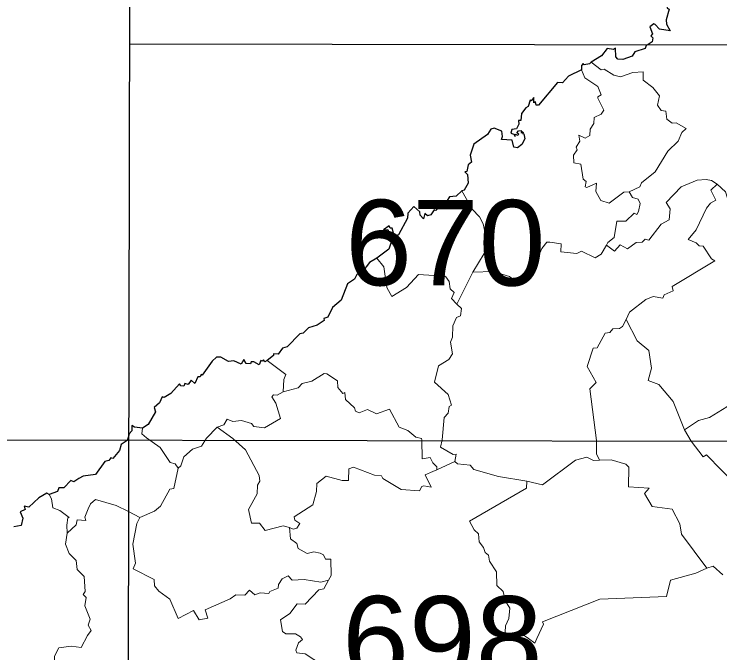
# Model space of a CAD drawing. Extents: x 483840 to 488445, y 4386047 to 4389027.
# Drawn here: x 487952.7 to 488113.7, y 4388006.1 to 4388151.7 of the extents above; entities that cross this region are included whole.
import ezdxf
from ezdxf.enums import TextEntityAlignment as Align

# ---------------------------------------------------------------- set-up
doc = ezdxf.new("R2010")
doc.units = 0
doc.header["$LTSCALE"] = 4
doc.linetypes.add('DOTTED', pattern=[1.5, 0.3, -1.2])
for name, color, linetype, lineweight in [('1', 7, 'Continuous', 13), ('2', 7, 'DOTTED', 13), ('3', 7, 'Continuous', 25)]:
    doc.layers.add(name, color=color, linetype=linetype, lineweight=lineweight)

msp = doc.modelspace()

# ---------------------------------------------------------------- linework, layer by layer
at = {"layer": '1', "lineweight": 25}
for p, q in [((487978.6, 4387873.99), (487979.3, 4388235.3)), ((487979.13, 4388144.96), (488394.81, 4388144.16)), ((487840.39, 4388054.9), (488394.63, 4388053.84))]:
    msp.add_line(p, q, dxfattribs=at)
at = {"layer": '3', "lineweight": 13}
for p, q in [((488074.25, 4388099.74), (488074.92, 4388099.74)), ((488087.85, 4388099.09), (488088.13, 4388099.68)), ((488057.38, 4388092.94), (488053.69, 4388085.65)), ((487999.04, 4388057.56), (488002.62, 4388055.03)), ((488053.23, 4388049.76), (488049.16, 4388047.86)), ((488049.16, 4388047.86), (488048.19, 4388047.51)), ((487978.82, 4388038.34), (487981.44, 4388036.98))]:
    msp.add_line(p, q, dxfattribs=at)
at = {"layer": '3'}
msp.add_line((487978.96, 4388056.07), (487978.76, 4388055.2), dxfattribs=at)
for points in [[(488109.21, 4388156.83), (488108.27, 4388156.85), (488107.5, 4388155.16), (488106.74, 4388154.73), (488106.29, 4388155.64), (488104.82, 4388156.58), (488103.69, 4388156.53), (488102.64, 4388155.81), (488101.54, 4388154), (488101.66, 4388153.1), (488102.11, 4388152.87), (488101.42, 4388150.45), (488101.52, 4388149.41), (488102.36, 4388147.91), (488099.88, 4388148.26), (488098.92, 4388149.35)], [(488098.92, 4388149.35), (488098.59, 4388149.53), (488097.72, 4388148.84), (488098.34, 4388147.23), (488097.91, 4388146.79), (488098.39, 4388146.28), (488098.22, 4388145.4), (488097.33, 4388144.8)], [(488097.33, 4388144.8), (488096.86, 4388144.6), (488096.63, 4388143.9), (488094.29, 4388143.12), (488093.69, 4388142.17), (488091.56, 4388141.39), (488090.4, 4388141.42), (488089.98, 4388142), (488089.87, 4388143.99), (488089.44, 4388143.67), (488087.97, 4388143.91), (488086.68, 4388142.25), (488084.32, 4388140.8)], [(488084.32, 4388140.8), (488083.98, 4388140.38), (488082.74, 4388140.17), (488082.53, 4388140.45), (488082.13, 4388139.98), (488082.15, 4388139.06)], [(488082.15, 4388139.06), (488079.19, 4388137.55), (488077.8, 4388136.08), (488076.65, 4388136.13), (488072.28, 4388131), (488071.76, 4388130.98), (488071.61, 4388131.71), (488071.26, 4388131.51), (488071.23, 4388132.73), (488070.66, 4388131.92), (488070.44, 4388132.13), (488069.93, 4388130.63), (488069.43, 4388130.33)], [(488069.43, 4388130.33), (488068.41, 4388129.09), (488068.26, 4388127.51), (488067.78, 4388127.46), (488067.86, 4388126.66), (488067.28, 4388125.58), (488066.27, 4388125.44), (488066, 4388124.61), (488066.72, 4388124.38), (488067.03, 4388123.82), (488066.98, 4388124.39), (488067.63, 4388124.14), (488067.8, 4388124.39), (488067.39, 4388124.66), (488067.79, 4388125.15), (488068.36, 4388125.16), (488068.46, 4388124.62), (488068.53, 4388125), (488068.87, 4388124.74), (488068.67, 4388124.55), (488069, 4388124.47), (488069.18, 4388123.32), (488068.53, 4388121.97), (488067.54, 4388121.26), (488066.71, 4388121.37), (488066.3, 4388122.96), (488063.91, 4388123.18), (488064.08, 4388123.84)], [(488064.08, 4388123.84), (488063.94, 4388125.03), (488062.18, 4388125.76), (488061.45, 4388125.49), (488060.71, 4388124.3), (488057.57, 4388122.1), (488056.7, 4388119.54), (488057.05, 4388118), (488056.25, 4388117.35), (488055.98, 4388115.84), (488055.54, 4388115.8), (488056.13, 4388115.18), (488056.29, 4388113.16), (488055.33, 4388111.59), (488054.84, 4388111.45)], [(488054.84, 4388111.45), (488053.57, 4388110.21), (488052.01, 4388110.09), (488051.35, 4388108.99), (488050.87, 4388108.97), (488048.88, 4388106.95), (488048.54, 4388107.12)], [(488048.54, 4388107.12), (488047.74, 4388106), (488046.99, 4388105.77), (488046.36, 4388106.31), (488046.07, 4388105.03), (488045.34, 4388105.89), (488045.29, 4388106.69), (488043.92, 4388107.91), (488042.53, 4388106.35), (488042.46, 4388105.21), (488040.43, 4388101.38), (488039.51, 4388100.91), (488038.97, 4388102.9)], [(488038.97, 4388102.9), (488038.46, 4388102.92), (488038.28, 4388103.44), (488036.94, 4388102.53), (488037.97, 4388102.61), (488038.79, 4388099.94)], [(488038.79, 4388099.94), (488038.2, 4388098.17), (488035.44, 4388096.1)], [(488035.44, 4388096.1), (488033.8, 4388095.09), (488032.05, 4388092.86), (488030.91, 4388092.37), (488030.34, 4388091.3), (488028.73, 4388090.22), (488027.35, 4388086.56), (488025.33, 4388084.82), (488024.25, 4388082.65), (488023.38, 4388082.36), (488023.45, 4388081.86)], [(488023.45, 4388081.86), (488021.86, 4388080.83), (488019.89, 4388080.22), (488018.66, 4388079.03), (488017.9, 4388078.85), (488014.99, 4388075.87), (488013.91, 4388075.62), (488012.92, 4388074.23), (488011.92, 4388074.32), (488011.9, 4388073.93), (488010.42, 4388072.74)], [(488010.42, 4388072.74), (488009.92, 4388072.48), (488009.62, 4388072.95), (488009.33, 4388072.64), (488008.97, 4388072.81), (488008.64, 4388071.82), (488007.44, 4388072.49), (488006.77, 4388072.48), (488006.65, 4388071.98), (488005.66, 4388072.06), (488005.13, 4388072.97), (488004.55, 4388071.91), (488002.86, 4388072.68), (488001.66, 4388072.52), (487999.87, 4388073.55), (487998.92, 4388073.52), (487997.87, 4388072.65), (487995.59, 4388069.4)], [(487995.59, 4388069.4), (487995.36, 4388069.62), (487995.2, 4388069.09), (487994.6, 4388069.02), (487993.93, 4388067.55), (487993.11, 4388068.3), (487992.4, 4388067.31), (487991.64, 4388067.55), (487991.42, 4388066.9), (487990.73, 4388066.97), (487990.44, 4388067.49), (487988.47, 4388065.26), (487986.98, 4388064.34), (487986.49, 4388064.51), (487985.86, 4388063.11), (487984.67, 4388062.04), (487984.95, 4388061.05)], [(487984.95, 4388061.05), (487983.29, 4388058.17), (487981.99, 4388057.38)], [(487981.99, 4388057.38), (487980.16, 4388057.56), (487979.6, 4388057.95), (487979.57, 4388056.76), (487978.96, 4388056.07)], [(487978.76, 4388055.2), (487978.5, 4388054.54), (487977.15, 4388053.64), (487976.79, 4388052.26), (487975.28, 4388050.45), (487974.79, 4388050.57), (487974.33, 4388049.98), (487973.44, 4388049.76), (487971.29, 4388046.8), (487968.51, 4388046.4), (487967.47, 4388045.86)], [(487967.47, 4388045.86), (487966.35, 4388045.1), (487965.65, 4388045.41), (487964.11, 4388043.76), (487962.96, 4388043.73), (487962.67, 4388042.93), (487960.73, 4388042.23)], [(487960.73, 4388042.23), (487960.22, 4388042.52), (487958.39, 4388041.46), (487956.12, 4388039.38), (487955.03, 4388039.6), (487955.28, 4388038.81), (487954.1, 4388038.28), (487954.75, 4388036.84), (487954.39, 4388035.2), (487952.69, 4388034.85)]]:
    msp.add_lwpolyline(points, dxfattribs=at)
at = {"layer": '3', "lineweight": 13}
for points in [[(488084.32, 4388140.8), (488086.58, 4388139.06), (488087.31, 4388139.15), (488089.49, 4388137.83), (488090.99, 4388137.43), (488093.82, 4388138.39), (488096.18, 4388138.58), (488096.21, 4388136.7), (488098.37, 4388135.03), (488099.92, 4388133.07), (488099.43, 4388130.95), (488100.26, 4388129.76), (488101.33, 4388129.58), (488101.57, 4388127.76), (488102.78, 4388126.88), (488103.73, 4388126.95), (488105.95, 4388125.66), (488105.03, 4388124.74), (488104.13, 4388122.8), (488101.84, 4388120.52), (488098.88, 4388115.76), (488095.78, 4388113.28), (488095.45, 4388112.37), (488093, 4388111.23)], [(488085.86, 4388132.53), (488085.83, 4388132.87), (488086.59, 4388133.31), (488085.82, 4388135.21), (488082.9, 4388137.21), (488082.15, 4388139.06)], [(488093, 4388111.23), (488091.79, 4388111.16), (488088.43, 4388108.67), (488086.55, 4388109.27), (488085.36, 4388111.27), (488085.51, 4388113.17), (488083.34, 4388112.18), (488082.99, 4388112.36), (488083.21, 4388113.55), (488082.48, 4388114.11), (488081.95, 4388117.52), (488080.34, 4388117.81), (488080.32, 4388119.6), (488081.17, 4388120.82), (488080.94, 4388121.38), (488081.77, 4388122.74), (488081.53, 4388124.11), (488082.96, 4388123.48), (488084.02, 4388124.08), (488084.1, 4388125.47), (488084.92, 4388126.8), (488085.03, 4388128.14), (488086.63, 4388128.91), (488087.25, 4388129.8), (488085.86, 4388132.53)], [(488113.04, 4388112.95), (488111.76, 4388113.82), (488110.52, 4388114.02), (488108.46, 4388113.87), (488104.85, 4388112.36), (488101.39, 4388108.75), (488102.37, 4388107.31), (488102.13, 4388104.86), (488100.3, 4388103.82), (488097.45, 4388100.17), (488096.64, 4388100.4), (488095.92, 4388099.73), (488094.58, 4388099.64)], [(488113.04, 4388112.95), (488111.62, 4388111.6), (488112.77, 4388109.34), (488111.52, 4388108.64), (488110.59, 4388107.46), (488108.3, 4388102.57), (488106.44, 4388100.35), (488108.23, 4388099.58)], [(488113.04, 4388112.95), (488114.99, 4388111.18), (488115.38, 4388109.76), (488116.38, 4388109.5), (488117.02, 4388107.33), (488117.72, 4388106.93)], [(488054.84, 4388111.45), (488057.19, 4388107.29), (488058.9, 4388105.49), (488059.73, 4388103.9), (488060.36, 4388100.76), (488060.88, 4388099.81)], [(488093, 4388111.23), (488093.74, 4388109.94), (488095.05, 4388109.53), (488095.53, 4388108.56), (488095.13, 4388106.7), (488094.73, 4388106.05), (488094.14, 4388106.35), (488092.2, 4388104.52), (488090.2, 4388104.51), (488089.54, 4388100.84), (488088.13, 4388099.68)], [(488057.38, 4388092.94), (488061.21, 4388099.27), (488060.88, 4388099.81)], [(488057.38, 4388092.94), (488062.01, 4388093.08), (488065.73, 4388091.89), (488067.62, 4388090.43), (488069.89, 4388092.95), (488070.32, 4388094.19), (488072.32, 4388096.56), (488073.1, 4388098.33), (488074.25, 4388099.74)], [(488087.85, 4388099.09), (488086.57, 4388097), (488085.2, 4388096.19), (488082.12, 4388097.73), (488081.04, 4388097.19), (488077.39, 4388097.51), (488077.5, 4388099.33), (488074.92, 4388099.74)], [(488087.85, 4388099.09), (488089.65, 4388097.68), (488090.93, 4388099.11), (488092.6, 4388098.22), (488094.58, 4388099.64)], [(488108.23, 4388099.58), (488108.98, 4388098.94), (488109.84, 4388098.86), (488111.74, 4388095.93), (488112.51, 4388095.48), (488102.76, 4388089.62), (488103.02, 4388088.66), (488100.98, 4388087.74), (488100.67, 4388086.99), (488098.44, 4388087.33), (488096.82, 4388086.65), (488093.05, 4388083.81), (488092.27, 4388082.13)], [(488035.44, 4388096.1), (488037.03, 4388094.12), (488037.76, 4388089.45), (488038.89, 4388087.4), (488042.21, 4388089.42), (488044.96, 4388092.39), (488048.45, 4388092.14)], [(488053.69, 4388085.65), (488052.45, 4388086.89), (488053.1, 4388088.3), (488052.14, 4388089.1), (488051.93, 4388090.81), (488051.22, 4388091.83), (488050.38, 4388092.4), (488048.45, 4388092.14)], [(488053.69, 4388085.65), (488054.72, 4388084.65), (488054.51, 4388082.95), (488053.58, 4388082.54), (488052.78, 4388080.67), (488052.73, 4388078.13), (488052.27, 4388076.98), (488052.67, 4388074.29), (488051.85, 4388073), (488049.53, 4388071.55), (488048.6, 4388067.8), (488051.72, 4388065.04), (488052.51, 4388062.58), (488051.95, 4388062.29), (488051.73, 4388060.76), (488050.77, 4388059.76), (488050.33, 4388054.7)], [(488092.27, 4388082.13), (488091.44, 4388080.49), (488090.78, 4388080.04), (488089.27, 4388080.03), (488088.55, 4388079.15), (488087.5, 4388079), (488085.71, 4388075.64), (488084.8, 4388075.56), (488083.41, 4388071.4), (488085.45, 4388067.77), (488084.05, 4388066.35), (488085.55, 4388054.53)], [(488092.27, 4388082.13), (488094.78, 4388077.28), (488097.49, 4388075.03), (488098.07, 4388071.04), (488097.33, 4388068.23), (488099.78, 4388067.28), (488103.05, 4388063.45), (488105.62, 4388057.01), (488107.11, 4388054.42)], [(488010.42, 4388072.74), (488014.74, 4388069.56), (488014.24, 4388068.42), (488014.13, 4388065.6)], [(488014.13, 4388065.6), (488017.52, 4388066.58), (488018.39, 4388067.51), (488020.63, 4388068.05), (488023.46, 4388069.84), (488024.03, 4388069.73), (488026.52, 4388068.15), (488026.58, 4388066.61), (488027.71, 4388065.28), (488028.17, 4388065.46), (488028.32, 4388063.88), (488030.36, 4388062.02), (488030.6, 4388061.23), (488031.41, 4388060.84), (488033.3, 4388061.59), (488035.34, 4388060.63), (488038.32, 4388061.67), (488040.55, 4388057.55), (488042.55, 4388056.81), (488044.35, 4388055.3), (488045.65, 4388055.03), (488045.69, 4388054.73)], [(488014.13, 4388065.6), (488012.71, 4388064.84), (488011.9, 4388064.95), (488011.54, 4388064.5), (488012.43, 4388063.03), (488013.47, 4388059.54), (488009.82, 4388057.42), (488007.38, 4388057.7), (488006.88, 4388058.38), (488004.56, 4388059.09), (488002.6, 4388058.86), (488001.34, 4388059.37), (488000.57, 4388058.15), (487999.04, 4388057.56), (487996.64, 4388055.07)], [(488105.62, 4388057.01), (488108.78, 4388059.1), (488111.28, 4388059.81), (488115.25, 4388062.24), (488117.55, 4388064.55)], [(487981.99, 4388057.38), (487981.87, 4388056.08), (487982.9, 4388055.17)], [(487982.9, 4388055.17), (487986.01, 4388052.93), (487988.33, 4388049.52), (487989.44, 4388049.2), (487990.14, 4388048.25)], [(487996.64, 4388055.07), (487995.45, 4388053.26), (487993.43, 4388052.58), (487991.48, 4388050.8), (487990.74, 4388048.75), (487990.14, 4388048.25)], [(488002.62, 4388055.03), (488005.48, 4388052.42), (488008.63, 4388046.54), (488008.77, 4388045.31), (488008.24, 4388044.36), (488008.15, 4388042.4), (488006.22, 4388038.84), (488006.85, 4388035.68), (488008.69, 4388035.67), (488009.99, 4388034.01), (488014.07, 4388035.07), (488015.54, 4388034.7)], [(488045.69, 4388054.73), (488045.79, 4388050.37), (488047.59, 4388050.7), (488048.2, 4388049.43)], [(488050.33, 4388054.7), (488049.97, 4388053.02), (488052.82, 4388051.34), (488053.52, 4388051.39), (488053.23, 4388049.76)], [(488085.55, 4388054.53), (488085.53, 4388051.51), (488086.21, 4388050.03)], [(488107.11, 4388054.42), (488109.86, 4388050.8), (488110.66, 4388051.29), (488117.47, 4388044.28)], [(488048.2, 4388049.43), (488049.1, 4388048.57), (488049.16, 4388047.86)], [(488069.69, 4388045.26), (488063.2, 4388046.35), (488057.55, 4388047.97), (488056.77, 4388048.93), (488053.85, 4388049.2), (488053.23, 4388049.76)], [(488086.21, 4388050.03), (488084.85, 4388049.95), (488083.34, 4388050.77), (488080.77, 4388050.08), (488073.2, 4388044.45), (488069.69, 4388045.26)], [(488086.21, 4388050.03), (488088.86, 4388050.15), (488092.23, 4388049.18), (488092.91, 4388048.48), (488092.83, 4388044.02), (488097.54, 4388043.66), (488096.52, 4388042.48), (488098.24, 4388039.53), (488102.76, 4388038.89), (488104.53, 4388035.55), (488104.92, 4388033.21), (488110.71, 4388025.43)], [(487990.14, 4388048.25), (487989.19, 4388043.63), (487988.26, 4388043.42), (487986.14, 4388039.57), (487984.78, 4388038.45), (487981.44, 4388036.98)], [(488015.54, 4388034.7), (488016.39, 4388034.35), (488017.22, 4388034.57), (488017.86, 4388035.59), (488016.72, 4388036.35), (488016.63, 4388037.11), (488020.86, 4388039.85), (488021.71, 4388042.9), (488021.8, 4388044.71), (488023.87, 4388046.4), (488027.53, 4388045.4), (488028.99, 4388045.42), (488029.05, 4388048.12), (488030.1, 4388048.43), (488034.94, 4388046.63), (488036.52, 4388046.48), (488036.79, 4388045.87), (488041.01, 4388043.41), (488045.19, 4388043.07), (488045.71, 4388044.07), (488046.18, 4388044.24), (488047.81, 4388043.92), (488046.44, 4388046.72), (488048.19, 4388047.51)], [(488069.69, 4388045.26), (488069.58, 4388043.7), (488056.61, 4388036.17), (488057.68, 4388034.2), (488058.65, 4388033.28), (488058.8, 4388031.44), (488059.77, 4388030.19), (488060.15, 4388028.98), (488060.91, 4388028.38), (488061.14, 4388027.02), (488062.71, 4388024.62), (488062.84, 4388021.48), (488064.23, 4388020.1), (488064.81, 4388017.95), (488065.8, 4388016.3), (488065.52, 4388013.94), (488064.79, 4388012.33), (488064.64, 4388009.47)], [(487960.73, 4388042.23), (487961.29, 4388041.27), (487961.54, 4388039.22), (487963.2, 4388038.59), (487965.27, 4388037.01), (487964.99, 4388036.93), (487964.77, 4388035.25), (487964.84, 4388033.44)], [(487964.84, 4388033.44), (487966.92, 4388035.35), (487967.12, 4388036.44), (487969.07, 4388036.34), (487968.9, 4388037.06), (487969.62, 4388038.98), (487970.18, 4388040.11), (487971.33, 4388041.1), (487975.98, 4388039.73), (487978.82, 4388038.34)], [(487981.44, 4388036.98), (487980.76, 4388035.64), (487979.78, 4388030.91), (487980.39, 4388026.57), (487979.89, 4388025.27), (487984.66, 4388022.85), (487984.78, 4388021.4), (487985.75, 4388020.21), (487988.28, 4388018.37), (487990.18, 4388013.94), (487993.63, 4388015.76), (487994.93, 4388013.64), (487996.88, 4388014.07), (487996.29, 4388015.94), (488002.02, 4388018.45), (488003.31, 4388019.36), (488005.37, 4388019.31), (488006.43, 4388020.44), (488007.64, 4388019.4), (488008.82, 4388019.84), (488010.82, 4388019.69), (488011.07, 4388020.11), (488012.98, 4388020.89), (488013.03, 4388021.74), (488013.87, 4388023.01), (488015.24, 4388023.69), (488016.15, 4388022.7), (488018.85, 4388022.86), (488022.67, 4388022.25), (488024.41, 4388022.73)], [(487964.84, 4388033.44), (487964.46, 4388030.92), (487965.27, 4388028.79), (487966.9, 4388027.21), (487967.15, 4388025.12), (487968.75, 4388023.57), (487968.96, 4388020.09), (487968.46, 4388019.47), (487969.17, 4388018.77), (487968.87, 4388016.88), (487970.06, 4388013.86), (487969.63, 4388012.48), (487970.33, 4388011.23), (487969.45, 4388010.12)], [(488015.54, 4388034.7), (488015.79, 4388032.11), (488017.18, 4388031.06), (488017.55, 4388029.9), (488019.58, 4388028.77), (488021.08, 4388029.19), (488022.56, 4388028.87), (488023.28, 4388028.45), (488023.75, 4388027.51), (488024.98, 4388027.53), (488025.01, 4388023.81), (488024.41, 4388022.73)], [(488110.71, 4388025.43), (488108.22, 4388024.31), (488102.42, 4388022.68), (488101.47, 4388018.96), (488086.3, 4388018.38), (488073.26, 4388013.2), (488073.49, 4388012.71), (488071.96, 4388009.43)], [(488114.31, 4388023.95), (488112.13, 4388025.87), (488110.71, 4388025.43)], [(488024.41, 4388022.73), (488023.39, 4388020.74), (488022.21, 4388020.51), (488019.11, 4388017.23), (488017.28, 4388017.32), (488015.59, 4388015.12), (488013.49, 4388013.7), (488013.97, 4388010.98), (488014.71, 4388010.49), (488016.93, 4388010.48), (488018.07, 4388009.76)], [(487969.45, 4388010.12), (487968.06, 4388007.38), (487965.76, 4388007.7), (487962.94, 4388007.28), (487961.95, 4388005.42), (487961.92, 4388002.51), (487961.13, 4388000.06), (487963.22, 4387998.37), (487964.92, 4387997.77), (487965.37, 4387995.93), (487966.74, 4387996.15), (487965.14, 4387993.92), (487963.19, 4387992.85), (487962.45, 4387990.37), (487958.7, 4387987.57), (487958.35, 4387985.3), (487956.45, 4387983.55), (487955.58, 4387980.55), (487954.04, 4387977.56)], [(488018.07, 4388009.76), (488018.47, 4388009.15), (488017.59, 4388008.42), (488016.99, 4388006.79), (488017.24, 4388006.18), (488019.09, 4388005.91), (488023.1, 4388003.37), (488025.12, 4388002.61), (488026.66, 4388000.82), (488025.07, 4388000.06), (488021.83, 4387997.57), (488019.77, 4387995.01), (488023.97, 4387991.47), (488025.47, 4387991.33), (488027.23, 4387990.24)], [(488064.64, 4388009.47), (488064.59, 4388009.1), (488065.31, 4388009.46)], [(488065.31, 4388009.46), (488068.31, 4388010.64), (488070.02, 4388009.44)], [(488070.02, 4388009.44), (488071.51, 4388008.36), (488071.96, 4388009.43)]]:
    msp.add_lwpolyline(points, dxfattribs=at)

# ---------------------------------------------------------------- texts
at = {"layer": '2', "width": 1.05}
for s, p in [('670', (488051.06, 4388089.88)), ('698', (488050.37, 4387999.58))]:
    msp.add_text(s, height=19.5, rotation=359.889, dxfattribs=at).set_placement(p, align=Align.CENTER)

doc.saveas('drawing.dxf')
